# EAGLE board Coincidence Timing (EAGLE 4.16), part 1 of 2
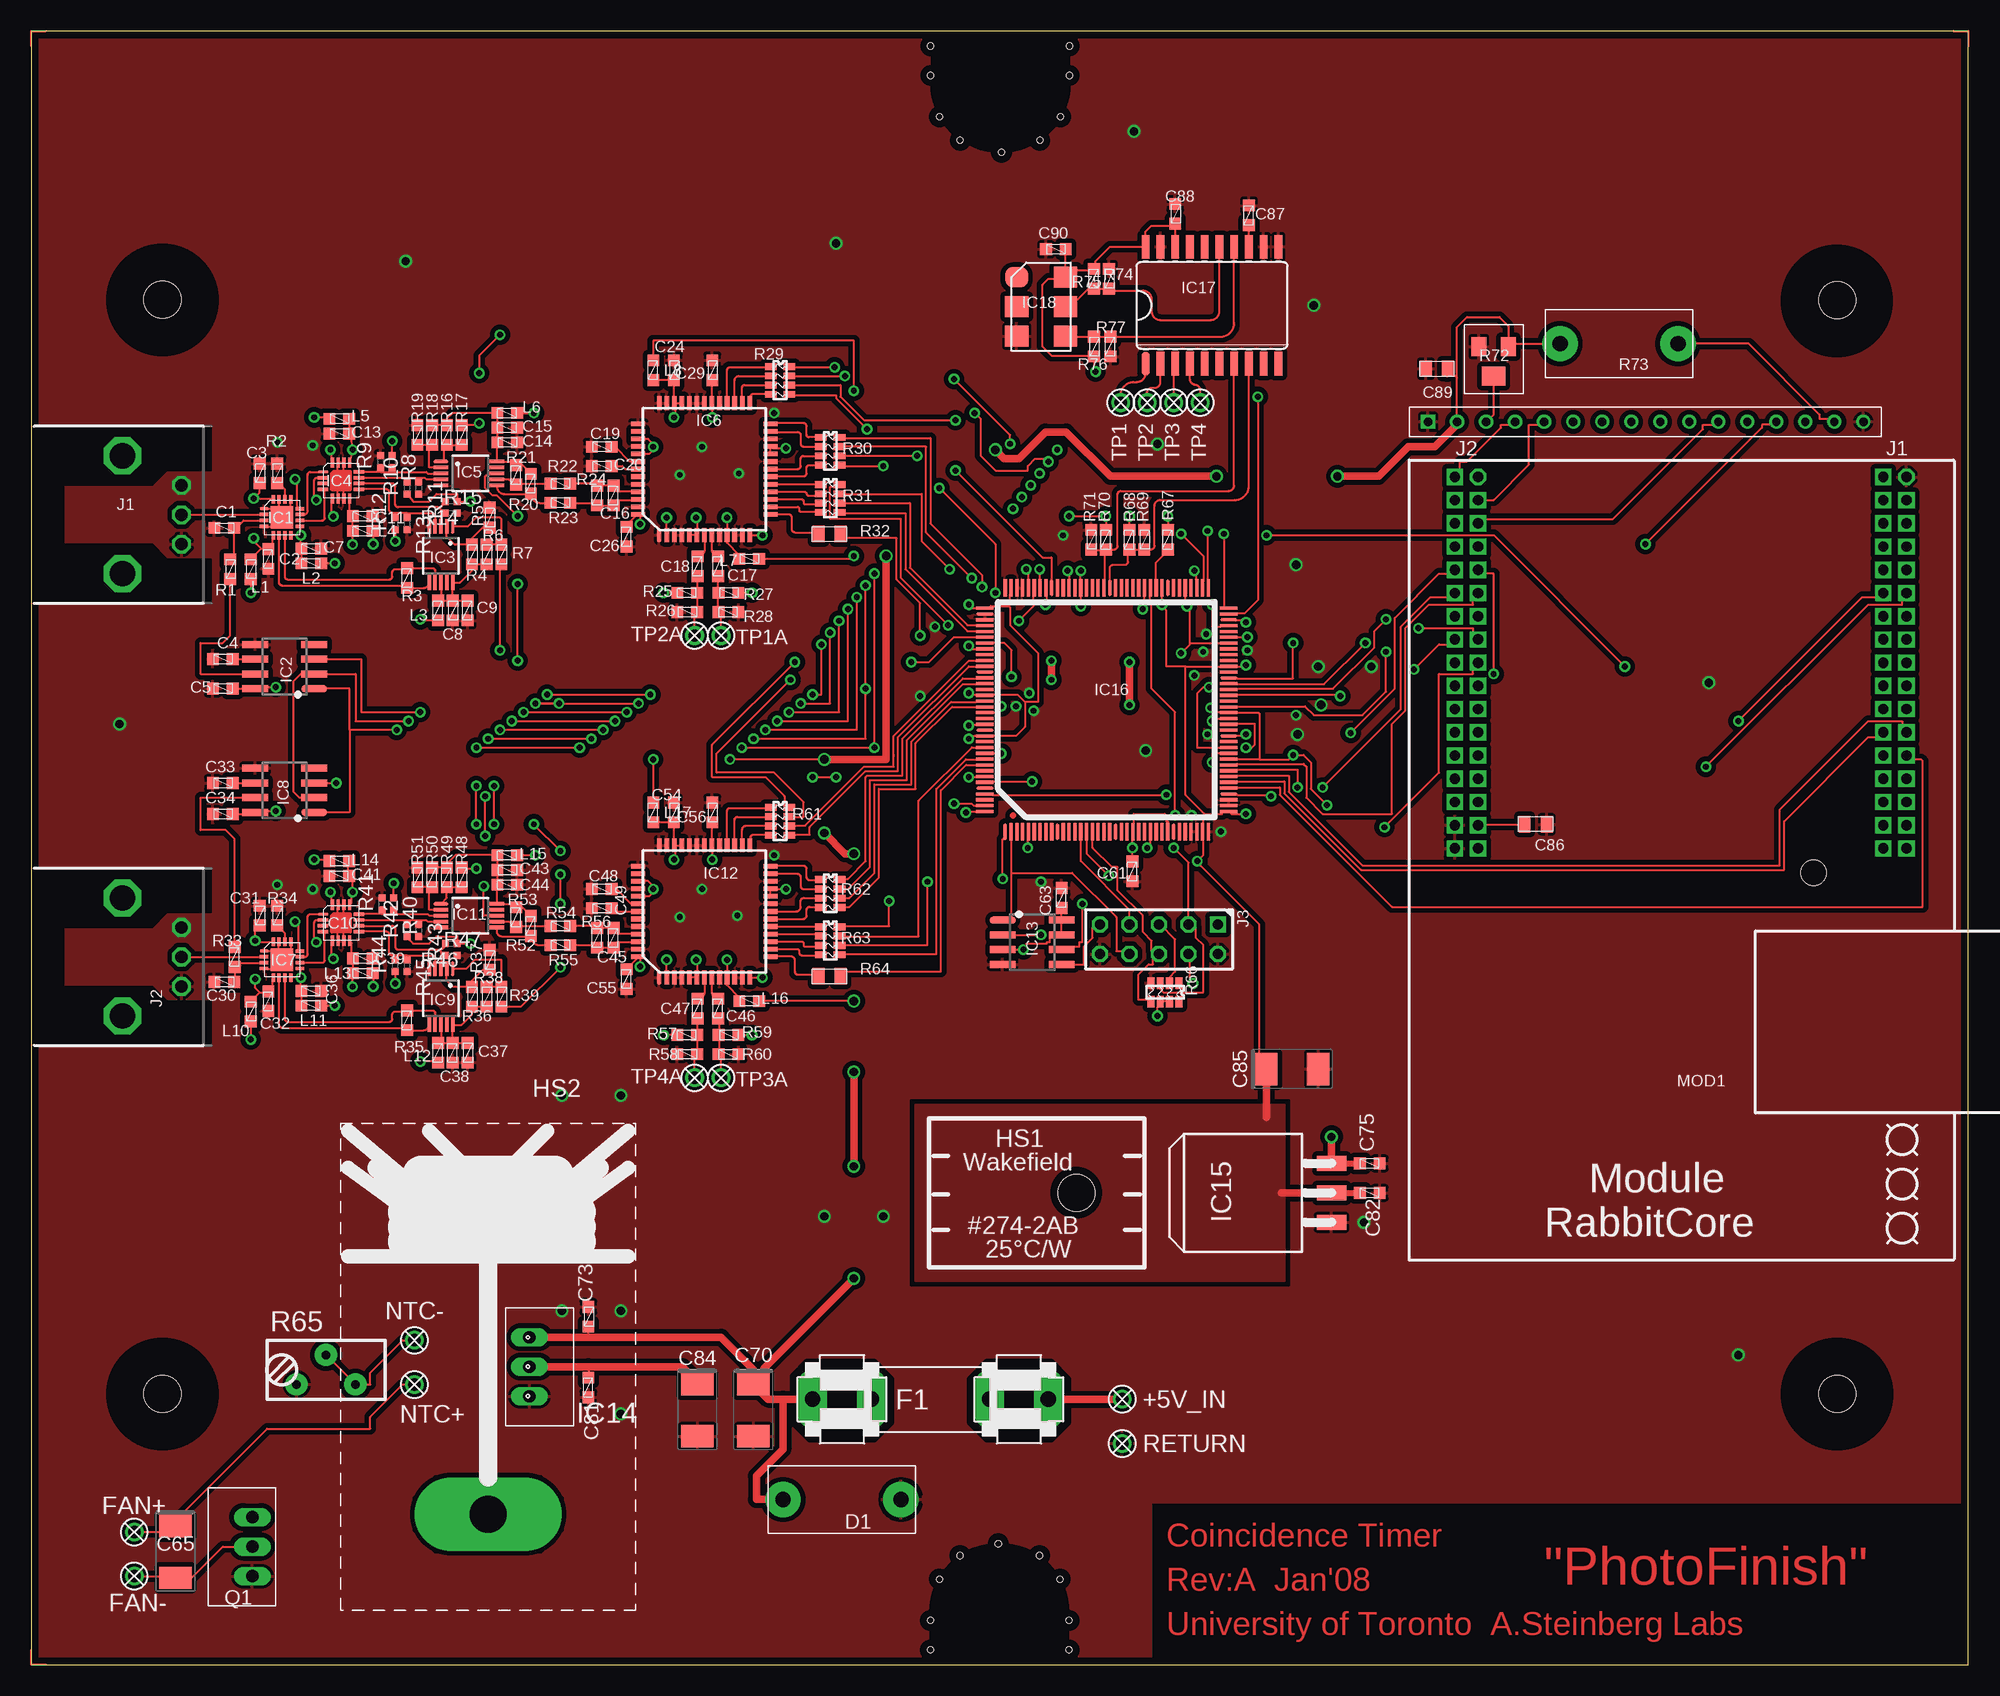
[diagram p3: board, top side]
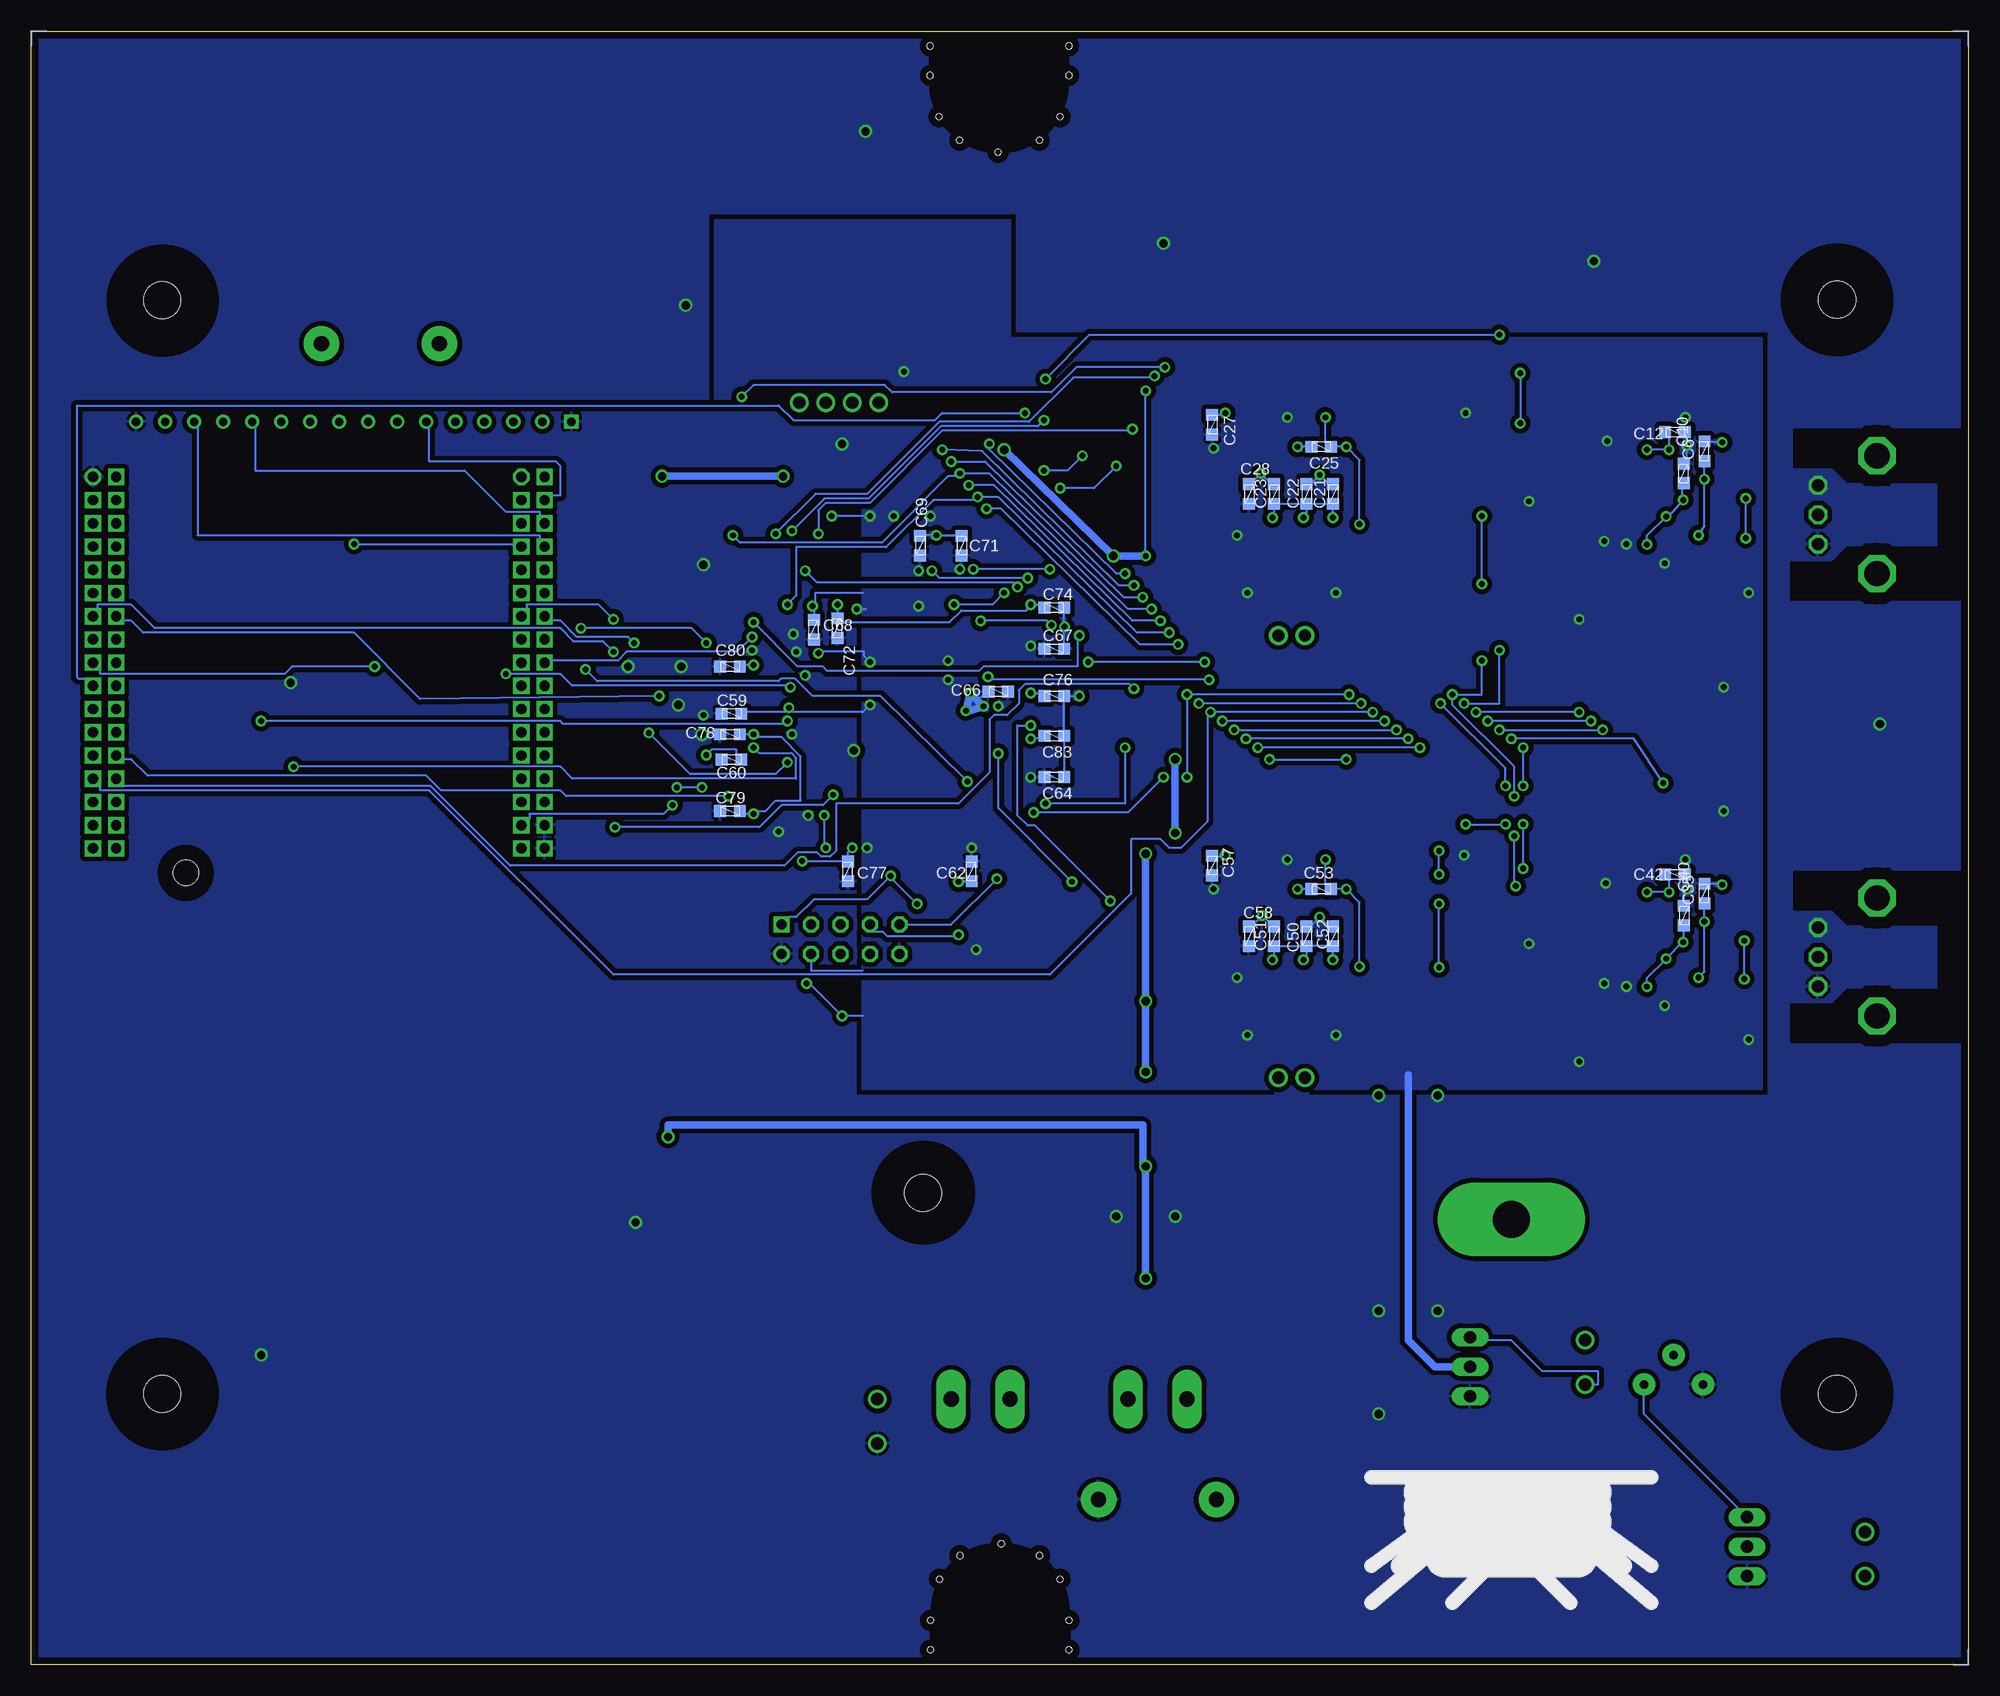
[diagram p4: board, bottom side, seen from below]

Size 166.88 x 140.72 mm. Coordinates in mm from the lower left corner, seen from the top.
Outline: 0,0 166.88,0 166.88,140.72 0,140.72 0,0
Copper layers (1*16): Top 0.035mm / dielectric 1.5mm / Bottom 0.035mm
Design rules "DRC standard check (7mil trace and gap, 20mil drill, etc)": minimum track width 7mil, minimum drill 20mil, track to track 7mil, track to pad 7mil, pad to pad 7mil, via to via 7mil, smd to smd 7mil, copper to edge 25mil, drill to drill 8mil, minimum pad ring 10mil, minimum via ring 8mil, stop-mask expansion 4mil, vias tented up to drill 0mil, thermal gap 10mil
Net classes: 0 default: clearance 0.406 mm; 1 50_Ohm: width 0.178 mm, drill 0.178 mm, clearance 0.406 mm
tRestrict: 19 lines
bRestrict: 56 lines

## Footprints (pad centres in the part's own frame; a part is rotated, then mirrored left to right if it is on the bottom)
TP-0.042 = drill 1.067 round: TP 0,0
1608(0603) = smd 1.016 x 1.016: 1 -0.85,0; 2 0.85,0
EIA-6032 = smd 1.905 x 2.794: + 2.54,0; - -1.905,0
2012(0805) = smd 1.016 x 1.397: 1 -1.27,0; 2 0.635,0
PASSIVE_0.4" = drill 1.321 pad 3.048 round: 1 -5.08,0; 2 5.08,0
DISPLAY1 = drill 0.711 square: 1 -20,0 | drill 0.711 round: 2 -17.5,0; 3 -15,0; 4 -12.5,0; 5 -10,0; 6 -7.5,0; 7 -5,0; 8 -2.5,0; 9 0,0; 10 2.5,0; 11 5,0; 12 7.5,0; 13 10,0; 14 12.5,0; 15 15,0; 16 17.5,0
FUSE = drill 1.321 pad 2.54 long: 1A -10.16,0; 1B -5.08,0; 2A 10.16,0; 2B 5.08,0
HEATSINK-3 = hole 3.175: 3.429,0
HEATSINK_529802B02(AAVID) = drill 3.175 pad 6.35 long: 1 -12.7,0; 2 12.7,0
LFCSP-16 = smd 0.75 x 0.3: 1 0,0; 2 0,-0.5; 3 0,-1; 4 0,-1.5; 9 3.1,-1.5; 10 3.1,-1; 11 3.1,-0.5; 12 3.1,0 | smd 0.3 x 0.75: 5 0.8,-2.3; 6 1.3,-2.3; 7 1.8,-2.3; 8 2.3,-2.3; 13 2.3,0.8; 14 1.8,0.8; 15 1.3,0.8; 16 0.8,0.8 | smd 1.95 x 1.95: PAD 1.55,-0.75
SOIC-8 = smd 0.6 x 2.2: 1 -1.27,-2.54; 2 0,-2.54; 3 1.27,-2.54; 4 2.54,-2.54; 5 2.54,2.54; 6 1.27,2.54; 7 0,2.54; 8 -1.27,2.54
MSOP10 = smd 0.305 x 1.27: 1 -1.016,-2.286; 2 -0.508,-2.286; 3 0,-2.286; 4 0.508,-2.286; 5 1.016,-2.286; 6 1.016,2.54; 7 0.508,2.54; 8 0,2.54; 9 -0.508,2.54; 10 -1.016,2.54
MLF-16 = smd 0.9 x 0.29: 1 0,0; 2 0,-0.5; 3 0,-1; 4 0,-1.5; 9 3.1,-1.5; 10 3.1,-1; 11 3.1,-0.5; 12 3.1,0 | smd 0.29 x 0.9: 5 0.8,-2.3; 6 1.3,-2.3; 7 1.8,-2.3; 8 2.3,-2.3; 13 2.3,0.8; 14 1.8,0.8; 15 1.3,0.8; 16 0.8,0.8
QFP52 = smd 1.2 x 0.4: 1 0,0; 2 0,-0.65; 3 0,-1.3; 4 0,-1.95; 5 0,-2.6; 6 0,-3.25; 7 0,-3.9; 8 0,-4.55; 9 0,-5.2; 10 0,-5.85; 11 0,-6.5; 12 0,-7.15; 13 0,-7.8; 27 11.4,-7.8; 28 11.4,-7.15; 29 11.4,-6.5; 30 11.4,-5.85; 31 11.4,-5.2; 32 11.4,-4.55; 33 11.4,-3.9; 34 11.4,-3.25; 35 11.4,-2.6; 36 11.4,-1.95; 37 11.4,-1.3; 38 11.4,-0.65; 39 11.4,0 | smd 0.4 x 1.2: 14 1.8,-9.6; 15 2.45,-9.6; 16 3.1,-9.6; 17 3.75,-9.6; 18 4.4,-9.6; 19 5.05,-9.6; 20 5.7,-9.6; 21 6.35,-9.6; 22 7,-9.6; 23 7.65,-9.6; 24 8.3,-9.6; 25 8.95,-9.6; 26 9.6,-9.6; 40 9.6,1.8; 41 8.95,1.8; 42 8.3,1.8; 43 7.65,1.8; 44 7,1.8; 45 6.35,1.8; 46 5.7,1.8; 47 5.05,1.8; 48 4.4,1.8; 49 3.75,1.8; 50 3.1,1.8; 51 2.45,1.8; 52 1.8,1.8
TO220-VERTICAL = drill 1.067 long: 1 -2.54,0; 2 0,0; 3 2.54,0
TO263 = smd 1.27 x 2.54: 1 -2.54,0; 2 0,0; 3 2.54,0
TQFP-144 = smd 1.5 x 0.27: 1 -10.29,8.29; 2 -10.29,7.79; 3 -10.29,7.29; 4 -10.29,6.79; 5 -10.29,6.29; 6 -10.29,5.79; 7 -10.29,5.29; 8 -10.29,4.79; 9 -10.29,4.29; 10 -10.29,3.79; 11 -10.29,3.29; 12 -10.29,2.79; 13 -10.29,2.29; 14 -10.29,1.79; 15 -10.29,1.29; 16 -10.29,0.79; 17 -10.29,0.29; 18 -10.29,-0.21; 19 -10.29,-0.71; 20 -10.29,-1.21; 21 -10.29,-1.71; 22 -10.29,-2.21; 23 -10.29,-2.71; 24 -10.29,-3.21; 25 -10.29,-3.71; 26 -10.29,-4.21; 27 -10.29,-4.71; 28 -10.29,-5.21; 29 -10.29,-5.71; 30 -10.29,-6.21; 31 -10.29,-6.71; 32 -10.29,-7.21; 33 -10.29,-7.71; 34 -10.29,-8.21; 35 -10.29,-8.71; 36 -10.29,-9.21; 73 10.71,-9.21; 74 10.71,-8.71; 75 10.71,-8.21; 76 10.71,-7.71; 77 10.71,-7.21; 78 10.71,-6.71; 79 10.71,-6.21; 80 10.71,-5.71; 81 10.71,-5.21; 82 10.71,-4.71; 83 10.71,-4.21; 84 10.71,-3.71; 85 10.71,-3.21; 86 10.71,-2.71; 87 10.71,-2.21; 88 10.71,-1.71; 89 10.71,-1.21; 90 10.71,-0.71; 91 10.71,-0.21; 92 10.71,0.29; 93 10.71,0.79; 94 10.71,1.29; 95 10.71,1.79; 96 10.71,2.29; 97 10.71,2.79; 98 10.71,3.29; 99 10.71,3.79; 100 10.71,4.29; 101 10.71,4.79; 102 10.71,5.29; 103 10.71,5.79; 104 10.71,6.29; 105 10.71,6.79; 106 10.71,7.29; 107 10.71,7.79; 108 10.71,8.29 | smd 0.27 x 1.5: 37 -8.54,-10.96; 38 -8.04,-10.96; 39 -7.54,-10.96; 40 -7.04,-10.96; 41 -6.54,-10.96; 42 -6.04,-10.96; 43 -5.54,-10.96; 44 -5.04,-10.96; 45 -4.54,-10.96; 46 -4.04,-10.96; 47 -3.54,-10.96; 48 -3.04,-10.96; 49 -2.54,-10.96; 50 -2.04,-10.96; 51 -1.54,-10.96; 52 -1.04,-10.96; 53 -0.54,-10.96; 54 -0.04,-10.96; 55 0.46,-10.96; 56 0.96,-10.96; 57 1.46,-10.96; 58 1.96,-10.96; 59 2.46,-10.96; 60 2.96,-10.96; 61 3.46,-10.96; 62 3.96,-10.96; 63 4.46,-10.96; 64 4.96,-10.96; 65 5.46,-10.96; 66 5.96,-10.96; 67 6.46,-10.96; 68 6.96,-10.96; 69 7.46,-10.96; 70 7.96,-10.96; 71 8.46,-10.96; 72 8.96,-10.96; 109 8.96,10.04; 110 8.46,10.04; 111 7.96,10.04; 112 7.46,10.04; 113 6.96,10.04; 114 6.46,10.04; 115 5.96,10.04; 116 5.46,10.04; 117 4.96,10.04; 118 4.46,10.04; 119 3.96,10.04; 120 3.46,10.04; 121 2.96,10.04; 122 2.46,10.04; 123 1.96,10.04; 124 1.46,10.04; 125 0.96,10.04; 126 0.46,10.04; 127 -0.04,10.04; 128 -0.54,10.04; 129 -1.04,10.04; 130 -1.54,10.04; 131 -2.04,10.04; 132 -2.54,10.04; 133 -3.04,10.04; 134 -3.54,10.04; 135 -4.04,10.04; 136 -4.54,10.04; 137 -5.04,10.04; 138 -5.54,10.04; 139 -6.04,10.04; 140 -6.54,10.04; 141 -7.04,10.04; 142 -7.54,10.04; 143 -8.04,10.04; 144 -8.54,10.04
SOIC-20W = smd 0.66 x 2.032: 1 -5.715,-5.029; 2 -4.445,-5.029; 3 -3.175,-5.029; 4 -1.905,-5.029; 5 -0.635,-5.029; 6 0.635,-5.029; 7 1.905,-5.029; 8 3.175,-5.029; 9 4.445,-5.029; 10 5.715,-5.029; 11 5.715,5.029; 12 4.445,5.029; 13 3.175,5.029; 14 1.905,5.029; 15 0.635,5.029; 16 -0.635,5.029; 17 -1.905,5.029; 18 -3.175,5.029; 19 -4.445,5.029; 20 -5.715,5.029
CONNER-WINFIELD_6 = smd 1.8 x 2: 1 -2.54,-2.095; 2 0,-2.095; 3 2.54,-2.095; 4 2.54,2.095; 5 0,2.095; 6 -2.54,2.095
CONN-BNC-AMP-TYPE3HORIZ = drill 1.067 octagon: CONDUCTOR 0,-12.7; SHIELD -2.54,-12.7 | drill 2.184 octagon: P$1 -5.08,-7.62; P$2 5.08,-7.62
CONN-2X5-BLASTER = drill 0.889 square: 1 0,5.08 | drill 0.889 octagon: 2 2.54,5.08; 3 0,2.54; 4 2.54,2.54; 5 0,0; 6 2.54,0; 7 0,-2.54; 8 2.54,-2.54; 9 0,-5.08; 10 2.54,-5.08
RABBIT_RCM3XXX = drill 0.889 octagon: 1-1 -18.16,-28.65; 2-1 18.74,-28.65 | drill 0.889 square: 1-2 -16.16,-28.65; 1-3 -18.16,-26.65; 1-4 -16.16,-26.65; 1-5 -18.16,-24.65; 1-6 -16.16,-24.65; 1-7 -18.16,-22.65; 1-8 -16.16,-22.65; 1-9 -18.16,-20.65; 1-10 -16.16,-20.65; 1-11 -18.16,-18.65; 1-12 -16.16,-18.65; 1-13 -18.16,-16.65; 1-14 -16.16,-16.65; 1-15 -18.16,-14.65; 1-16 -16.16,-14.65; 1-17 -18.16,-12.65; 1-18 -16.16,-12.65; 1-19 -18.16,-10.65; 1-20 -16.16,-10.65; 1-21 -18.16,-8.65; 1-22 -16.16,-8.65; 1-23 -18.16,-6.65; 1-24 -16.16,-6.65; 1-25 -18.16,-4.65; 1-26 -16.16,-4.65; 1-27 -18.16,-2.65; 1-28 -16.16,-2.65; 1-29 -18.16,-0.65; 1-30 -16.16,-0.65; 1-31 -18.16,1.35; 1-32 -16.16,1.35; 1-33 -18.16,3.35; 1-34 -16.16,3.35; 2-2 20.74,-28.65; 2-3 18.74,-26.65; 2-4 20.74,-26.65; 2-5 18.74,-24.65; 2-6 20.74,-24.65; 2-7 18.74,-22.65; 2-8 20.74,-22.65; 2-9 18.74,-20.65; 2-10 20.74,-20.65; 2-11 18.74,-18.65; 2-12 20.74,-18.65; 2-13 18.74,-16.65; 2-14 20.74,-16.65; 2-15 18.74,-14.65; 2-16 20.74,-14.65; 2-17 18.74,-12.65; 2-18 20.74,-12.65; 2-19 18.74,-10.65; 2-20 20.74,-10.65; 2-21 18.74,-8.65; 2-22 20.74,-8.65; 2-23 18.74,-6.65; 2-24 20.74,-6.65; 2-25 18.74,-4.65; 2-26 20.74,-4.65; 2-27 18.74,-2.65; 2-28 20.74,-2.65; 2-29 18.74,-0.65; 2-30 20.74,-0.65; 2-31 18.74,1.35; 2-32 20.74,1.35; 2-33 18.74,3.35; 2-34 20.74,3.35 | hole 2.184: -10.16,5.45
1005(0402) = smd 0.6 x 0.6: 1 -0.508,0; 2 0.508,0
PANASONIC_EXB-V8V(QUAD-R-PACK) = smd 1 x 0.59: 1A -0.8,1.2; 1B 0.8,1.2; 2A -0.8,0.4; 2B 0.8,0.4; 3A -0.8,-0.4; 3B 0.8,-0.4; 4A -0.8,-1.2; 4B 0.8,-1.2
BOURNS-3296Y = drill 0.711 pad 1.905 round: CCW 2.54,1.27; CW -2.54,1.27; W 0,-1.27
BOURNS_3214 = smd 1.651 x 1.27: CCW 1.27,-1.27; CW 1.27,1.27 | smd 1.651 x 2.032: W -1.27,0
CASE-HAMMOND-1598B/C = hole 3.175: 155.568,117.522; 155.573,23.317; 11.317,117.566; 11.317,23.316 | hole 0.508: 77.47,1.27; 77.47,3.81; 78.232,7.366; 80.01,9.398; 83.312,10.414; 86.868,9.398; 88.646,7.366; 89.408,3.81; 89.408,1.27; 89.43,139.43; 89.43,136.89; 88.668,133.334; 86.89,131.302; 83.588,130.286; 80.032,131.302; 78.254,133.334; 77.492,136.89; 77.492,139.43

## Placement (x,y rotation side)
+5V_IN  [TP-0.042]  93.98,22.86 0 top
C1  1nF  [1608(0603)]  16.64,97.92 0 top
C2  [1608(0603)]  20.45,95.25 90 top
C3  1nF  [1608(0603)]  19.68,102.62 270 top
C4  [1608(0603)]  16.51,86.61 0 top
C5  [1608(0603)]  16.51,84.07 0 top
C6  [1608(0603)]  22.73,104.52 90 bottom
C7  1nF  [1608(0603)]  24.13,96.14 180 top
C8  [1608(0603)]  36.32,90.81 270 top
C9  1nF  [1608(0603)]  37.59,90.81 90 top
C10  [1608(0603)]  24.51,102.62 90 bottom
C11  1nF  [1608(0603)]  28.57,98.93 180 top
C12  [1608(0603)]  25.27,106.17 0 bottom
C13  1nF  [1608(0603)]  26.54,106.05 0 top
C14  [1608(0603)]  41.02,105.28 0 top
C15  1nF  [1608(0603)]  41.02,106.55 180 top
C16  100pF  [1608(0603)]  50.16,100.71 90 top
C17  [1608(0603)]  59.18,94.61 90 top
C18  [1608(0603)]  57.4,94.61 90 top
C19  [1608(0603)]  49.15,104.9 0 top
C20  out  [1608(0603)]  49.15,103.25 0 top
C21  [1608(0603)]  54.74,100.84 270 bottom
C22  [1608(0603)]  57.02,100.84 270 bottom
C23  [1608(0603)]  59.82,100.84 270 bottom
C24  [1608(0603)]  55.37,111.51 270 top
C25  [1608(0603)]  55.75,104.9 0 bottom
C26  [1608(0603)]  51.31,97.16 90 top
C27  [1608(0603)]  65.15,106.81 270 bottom
C28  [1608(0603)]  61.98,100.84 270 bottom
C29  [1608(0603)]  58.67,111.51 270 top
C30  1nF  [1608(0603)]  16.64,58.8 0 top
C31  [1608(0603)]  19.68,64.52 270 top
C32  1nF  [1608(0603)]  20.45,57.15 90 top
C33  [1608(0603)]  16.51,75.95 0 top
C34  [1608(0603)]  16.51,73.28 0 top
C35  [1608(0603)]  22.73,66.42 90 bottom
C36  1nF  [1608(0603)]  24.13,58.04 180 top
C37  [1608(0603)]  37.59,52.7 270 top
C38  1nF  [1608(0603)]  36.32,52.7 90 top
C39  [1608(0603)]  28.57,60.83 0 top
C40  1nF  [1608(0603)]  24.51,64.52 270 bottom
C41  [1608(0603)]  26.54,67.94 180 top
C42  1nF  [1608(0603)]  25.27,68.07 180 bottom
C43  [1608(0603)]  41.02,68.45 0 top
C44  1nF  [1608(0603)]  41.02,67.18 180 top
C45  100pF  [1608(0603)]  50.16,62.61 90 top
C46  [1608(0603)]  59.18,56.52 90 top
C47  [1608(0603)]  57.4,56.52 90 top
C48  [1608(0603)]  49.15,66.8 0 top
C49  out  [1608(0603)]  49.15,65.15 0 top
C50  [1608(0603)]  57.02,62.74 270 bottom
C51  [1608(0603)]  59.82,62.74 270 bottom
C52  [1608(0603)]  54.74,62.74 270 bottom
C53  [1608(0603)]  55.75,66.8 0 bottom
C54  [1608(0603)]  55.37,73.41 270 top
C55  [1608(0603)]  51.31,59.05 90 top
C56  [1608(0603)]  58.67,73.41 270 top
C57  [1608(0603)]  65.15,68.83 270 bottom
C58  [1608(0603)]  61.98,62.74 270 bottom
C59  [1608(0603)]  106.55,81.92 0 bottom
C60  [1608(0603)]  106.55,77.98 0 bottom
C61  [1608(0603)]  94.87,68.33 90 top
C62  [1608(0603)]  85.85,68.33 90 bottom
C63  [1608(0603)]  88.77,66.04 90 top
C64  [1608(0603)]  78.74,76.45 180 bottom
C65  33uF  [EIA-6032]  12.45,9.4 90 top
C66  [1608(0603)]  83.57,83.82 0 bottom
C67  [1608(0603)]  78.74,87.5 180 bottom
C68  [1608(0603)]  99.44,89.15 90 bottom
C69  [1608(0603)]  90.3,96.39 270 bottom
C70  33uF  [EIA-6032]  62.23,21.59 90 top
C71  [1608(0603)]  86.74,96.39 270 bottom
C72  [1608(0603)]  97.41,89.28 90 bottom
C73  0.1uF  [1608(0603)]  48.01,29.97 270 top
C74  [1608(0603)]  78.74,91.06 180 bottom
C75  0.1uF  [1608(0603)]  115.32,43.18 180 top
C76  [1608(0603)]  78.74,83.44 180 bottom
C77  [1608(0603)]  96.52,68.33 90 bottom
C78  [1608(0603)]  106.68,80.14 0 bottom
C79  [1608(0603)]  106.68,73.53 0 bottom
C80  [1608(0603)]  106.68,85.98 0 bottom
C81  0.1uF  [1608(0603)]  48.01,23.88 90 top
C82  0.1uF  [1608(0603)]  115.32,40.64 180 top
C83  [1608(0603)]  78.74,80.01 180 bottom
C84  33uF  [EIA-6032]  57.4,21.59 90 top
C85  33uF  [EIA-6032]  108.97,51.31 180 top
C86  [2012(0805)]  129.29,72.39 180 top
C87  [1608(0603)]  104.9,124.84 90 top
C88  [1608(0603)]  98.55,124.97 270 top
C89  [2012(0805)]  121.41,111.63 0 top
C90  [1608(0603)]  88.27,121.92 0 top
D1  1N5339  [PASSIVE_0.4"]  69.85,14.22 180 top
DIS  [DISPLAY1]  140.34,107.06 0 top
F1  2A  [FUSE]  77.47,22.86 0 top
FAN+  [TP-0.042]  8.89,11.43 180 top
FAN-  [TP-0.042]  8.89,7.62 180 top
HS1  Wakefield 274-2AB  [HEATSINK-3]  86.61,40.64 0 top
HS2  Aavid 531102B00000G  [HEATSINK_529802B02(AAVID)]  39.37,25.65 90 top
IC1  ADCMP572BCP  [LFCSP-16]  20.07,99.57 0 top
IC2  LTC1453CS8  [SOIC-8]  21.84,85.34 90 top
IC3  SY55851AUK  [MSOP10]  35.31,95.76 180 top
IC4  SY58012U  [MLF-16]  25.15,102.74 0 top
IC5  SY55851AUK  [MSOP10]  37.59,102.62 270 top
IC6  AD9432BS?-105  [QFP52]  54.1,97.28 90 top
IC7  ADCMP572BCP  [LFCSP-16]  20.07,61.47 0 top
IC8  LTC1453CS8  [SOIC-8]  21.84,74.68 90 top
IC9  SY55851AUK  [MSOP10]  35.31,57.66 180 top
IC10  SY58012U  [MLF-16]  25.15,64.64 0 top
IC11  SY55851AUK  [MSOP10]  37.59,64.52 270 top
IC12  AD9432BS?-105  [QFP52]  54.1,59.18 90 top
IC13  EPCS4  [SOIC-8]  86.23,62.87 270 top
IC14  LM1086CT-3.3  [TO220-VERTICAL]  42.93,25.65 90 top
IC15  LM1086-ADJ  [TO263]  112.01,40.64 90 top
IC16  EP2C8T144C6  [TQFP-144]  92.2,82.04 90 top
IC17  MC100LVEL14DW  [SOIC-20W]  101.73,117.09 0 top
IC18  P143-100.0M  [CONNER-WINFIELD_6]  87,116.97 270 top
J1  Amp 227677-1  [CONN-BNC-AMP-TYPE3HORIZ]  0.25,99.06 90 top
J2  Amp 227677-1  [CONN-BNC-AMP-TYPE3HORIZ]  0.25,60.96 90 top
J3  2x5*  [CONN-2X5-BLASTER]  97.16,63.75 270 top
L1  [1608(0603)]  18.92,94.36 270 top
L2  [1608(0603)]  24.13,94.87 180 top
L3  [1608(0603)]  35.05,90.81 90 top
L4  [1608(0603)]  28.57,97.66 180 top
L5  [1608(0603)]  26.54,107.31 0 top
L6  [1608(0603)]  41.02,107.82 180 top
L7  [1608(0603)]  61.85,95.25 0 top
L8  [1608(0603)]  53.59,111.51 90 top
L10  [1608(0603)]  18.92,56.26 270 top
L11  [1608(0603)]  24.13,56.77 180 top
L12  [1608(0603)]  35.05,52.7 90 top
L13  [1608(0603)]  28.57,59.56 180 top
L14  [1608(0603)]  26.54,69.22 0 top
L15  [1608(0603)]  41.02,69.72 180 top
L16  [1608(0603)]  61.85,57.15 0 top
L17  [1608(0603)]  53.59,73.41 90 top
MOD1  RCM3200 & connectors  [RABBIT_RCM3XXX]  143.38,73.66 180 top
NTC+  [TP-0.042]  33.02,24.13 0 top
NTC-  [TP-0.042]  33.02,27.94 0 top
Q1  NDP6060L  [TO220-VERTICAL]  19.05,10.16 270 top
R1  200  [1608(0603)]  17.14,94.36 270 top
R2  1K  [1608(0603)]  21.21,102.62 270 top
R3  100  [1608(0603)]  32.38,93.6 90 top
R4  549  [1608(0603)]  37.97,95.63 270 top
R5  1.47K  [1608(0603)]  39.5,98.81 270 top
R6  1K  [1608(0603)]  39.24,95.63 270 top
R7  1K  [1608(0603)]  40.51,95.63 270 top
R8  127  [1005(0402)]  31.11,103.63 270 top
R9  82  [1005(0402)]  30.1,103.63 90 top
R10  127  [1005(0402)]  32.38,101.35 90 top
R11  82  [1005(0402)]  33.4,101.35 270 top
R12  127  [1005(0402)]  31.37,98.3 90 top
R13  82  [1005(0402)]  32.38,98.3 270 top
R14  127  [1005(0402)]  36.2,100.2 180 top
R15  82  [1005(0402)]  36.2,99.19 0 top
R16  1K  [1608(0603)]  35.81,105.92 90 top
R17  1K  [1608(0603)]  37.08,105.92 270 top
R18  549  [1608(0603)]  34.54,105.92 90 top
R19  1.47K  [1608(0603)]  33.27,105.92 270 top
R20  1K  [1608(0603)]  43.05,101.73 90 top
R21  1K  [1608(0603)]  41.78,102.49 90 top
R22  1  [1608(0603)]  45.59,101.73 0 top
R23  1  [1608(0603)]  45.59,100.08 0 top
R24  out  [1608(0603)]  48.77,100.71 90 top
R25  127  [1608(0603)]  56.52,92.33 180 top
R26  82.5  [1608(0603)]  56.52,90.68 0 top
R27  127  [1608(0603)]  60.07,92.33 0 top
R28  82.5  [1608(0603)]  60.07,90.68 180 top
R29  33  [PANASONIC_EXB-V8V(QUAD-R-PACK)]  64.52,110.62 0 top
R30  33  [PANASONIC_EXB-V8V(QUAD-R-PACK)]  68.83,104.52 0 top
R31  33  [PANASONIC_EXB-V8V(QUAD-R-PACK)]  68.83,100.46 0 top
R32  33  [2012(0805)]  69.09,97.41 0 top
R33  200  [1608(0603)]  17.53,60.96 90 top
R34  1K  [1608(0603)]  21.21,64.52 270 top
R35  100  [1608(0603)]  32.38,55.5 90 top
R36  549  [1608(0603)]  37.97,57.53 270 top
R37  1.47K  [1608(0603)]  39.5,60.71 270 top
R38  1K  [1608(0603)]  39.24,57.53 270 top
R39  1K  [1608(0603)]  40.51,57.53 270 top
R40  127  [1005(0402)]  31.24,65.53 270 top
R41  82  [1005(0402)]  30.23,65.53 90 top
R42  127  [1005(0402)]  32.38,63.25 90 top
R43  82  [1005(0402)]  33.4,63.25 270 top
R44  127  [1005(0402)]  31.37,60.2 90 top
R45  82  [1005(0402)]  32.38,60.2 270 top
R46  127  [1005(0402)]  36.2,62.1 180 top
R47  82  [1005(0402)]  36.2,61.09 0 top
R48  1K  [1608(0603)]  35.81,67.82 90 top
R49  1K  [1608(0603)]  37.08,67.82 270 top
R50  549  [1608(0603)]  34.54,67.82 90 top
R51  1.47K  [1608(0603)]  33.27,67.82 270 top
R52  1K  [1608(0603)]  43.05,63.63 90 top
R53  1K  [1608(0603)]  41.78,64.39 90 top
R54  1  [1608(0603)]  45.59,63.63 0 top
R55  1  [1608(0603)]  45.59,61.98 0 top
R56  out  [1608(0603)]  48.77,62.61 90 top
R57  127  [1608(0603)]  56.52,54.23 180 top
R58  82.5  [1608(0603)]  56.52,52.58 0 top
R59  127  [1608(0603)]  60.07,54.23 0 top
R60  82.5  [1608(0603)]  60.07,52.58 180 top
R61  33  [PANASONIC_EXB-V8V(QUAD-R-PACK)]  64.52,72.64 0 top
R62  33  [PANASONIC_EXB-V8V(QUAD-R-PACK)]  68.83,66.42 0 top
R63  33  [PANASONIC_EXB-V8V(QUAD-R-PACK)]  68.83,62.36 0 top
R64  33  [2012(0805)]  69.09,59.31 0 top
R65  3296Y-10K  [BOURNS-3296Y]  25.4,25.4 180 top
R66  10K  [PANASONIC_EXB-V8V(QUAD-R-PACK)]  97.66,57.91 270 top
R67  10K  [1608(0603)]  97.92,96.9 90 top
R68  127  [1608(0603)]  94.61,96.9 90 top
R69  82.5  [1608(0603)]  95.89,96.9 270 top
R70  127  [1608(0603)]  92.58,96.9 90 top
R71  82.5  [1608(0603)]  91.31,96.9 270 top
R72  3214W-10K  [BOURNS_3214]  125.98,112.27 90 top
R73  10/0.5W  [PASSIVE_0.4"]  136.78,113.79 180 top
R74  127  [1608(0603)]  91.57,119.38 90 top
R75  82.5  [1608(0603)]  92.84,119.38 270 top
R76  127  [1608(0603)]  91.57,113.54 270 top
R77  82.5  [1608(0603)]  92.96,113.54 90 top
RETURN  [TP-0.042]  93.98,19.05 0 top
TP1  [TP-0.042]  93.85,108.71 270 top
TP1A  [TP-0.042]  59.44,88.65 270 top
TP2  [TP-0.042]  96.14,108.71 270 top
TP2A  [TP-0.042]  57.15,88.65 270 top
TP3  [TP-0.042]  98.42,108.71 270 top
TP3A  [TP-0.042]  59.44,50.55 270 top
TP4  [TP-0.042]  100.71,108.71 270 top
TP4A  [TP-0.042]  57.15,50.55 270 top
U$80  [TITLEBLOCK_PCB]  not placed on the board
U$111  [CASE-HAMMOND-1598B/C]  0,0 0 top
